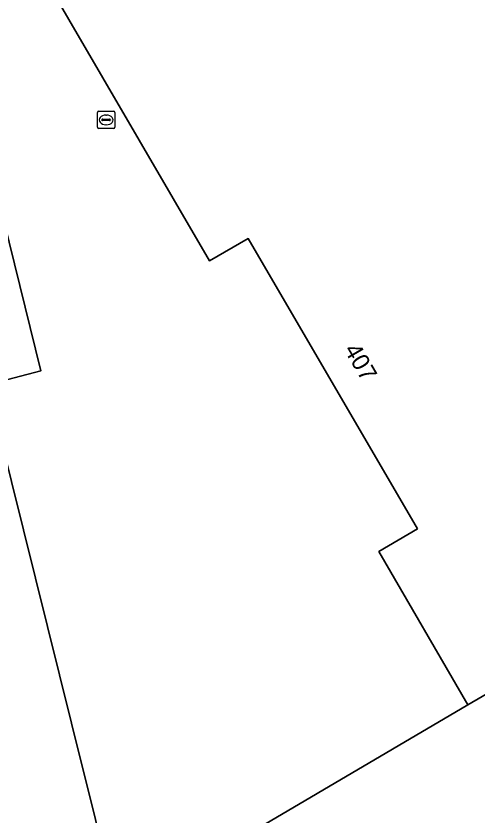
# Model space of a CAD drawing. Extents: x 161385 to 162589, y 388479 to 389756.
# Drawn here: x 162188.02 to 162214.6, y 388929.27 to 388975.29 of the extents above; entities that cross this region are included whole.
import ezdxf

# ---------------------------------------------------------------- set-up
doc = ezdxf.new("R2010")
doc.units = 0
for name, color, linetype in [('IMGEO_Erf', 7, 'Continuous'), ('IMGEO_Groenvoorziening', 7, 'Continuous'), ('IMGEO_Haag', 7, 'Continuous'), ('IMGEO_Pand', 7, 'Continuous'), ('IMGEO_Pand_nummerreeks', 7, 'Continuous'), ('IMGEO_Rijbaan_lokaal_gesloten', 7, 'Continuous'), ('IMGEO_Rioolput', 7, 'Continuous')]:
    doc.layers.add(name, color=color, linetype=linetype)

msp = doc.modelspace()

# ---------------------------------------------------------------- linework, layer by layer
at = {"layer": 'IMGEO_Erf'}
for points in [[(162205.565, 388889.805), (162226.358, 388916.854), (162240.417, 388950.904), (162224.076, 388941.428), (162229.276, 388932.462), (162223.571, 388918.583), (162206.409, 388908.625), (162196.702, 388925.403), (162214.07, 388935.626), (162208.932, 388944.442), (162211.169, 388945.746), (162201.412, 388962.483), (162199.18, 388961.18), (162188.976, 388978.704)], [(162183.768, 388977.824), (162184.88, 388973.335), (162189.456, 388954.856), (162186.365, 388954.055), (162191.224, 388934.569), (162202.309, 388890.111)]]:
    msp.add_lwpolyline(points, dxfattribs=at)
at = {"layer": 'IMGEO_Groenvoorziening'}
msp.add_lwpolyline([(162184.443, 388961.763), (162186.365, 388954.055), (162189.456, 388954.856), (162184.88, 388973.335)], dxfattribs=at)
at = {"layer": 'IMGEO_Haag'}
msp.add_lwpolyline([(162184.443, 388961.763), (162186.365, 388954.055), (162189.456, 388954.856), (162184.88, 388973.335)], dxfattribs=at)
at = {"layer": 'IMGEO_Pand'}
for points in [[(162260.806, 389000), (162264.508, 389009.017), (162258.602, 389019.221), (162225.572, 389000), (162188.976, 388978.704), (162199.18, 388961.18), (162201.412, 388962.483), (162211.169, 388945.746), (162208.932, 388944.442), (162214.07, 388935.626), (162224.076, 388941.428), (162240.417, 388950.904)], [(162224.076, 388941.428), (162214.07, 388935.626), (162196.702, 388925.403), (162206.409, 388908.625), (162223.571, 388918.583), (162229.276, 388932.462)]]:
    msp.add_lwpolyline(points, close=True, dxfattribs=at)
at = {"layer": 'IMGEO_Rijbaan_lokaal_gesloten'}
msp.add_lwpolyline([(162204.281, 388882.203), (162202.309, 388890.111), (162191.224, 388934.569), (162186.365, 388954.055), (162184.443, 388961.763)], dxfattribs=at)
at = {"layer": 'IMGEO_Rioolput'}
for p, q in [((162192.72, 388968.879), (162192.72, 388969.731)), ((162192.795, 388969.805), (162193.647, 388969.805)), ((162193.721, 388969.731), (162193.721, 388968.879)), ((162192.979, 388969.299), (162192.979, 388969.311)), ((162193.417, 388969.262), (162193.019, 388969.262)), ((162193.022, 388969.348), (162193.42, 388969.348)), ((162193.208, 388969.585), (162193.233, 388969.585)), ((162193.463, 388969.311), (162193.463, 388969.299)), ((162193.647, 388968.805), (162192.795, 388968.805)), ((162193.231, 388969.025), (162193.206, 388969.025))]:
    msp.add_line(p, q, dxfattribs=at)
for points in [[(162192.72, 388968.879), (162192.72, 388969.731)], [(162192.795, 388969.805), (162193.647, 388969.805)], [(162193.721, 388969.731), (162193.721, 388968.879)], [(162193.647, 388968.805), (162192.795, 388968.805)]]:
    msp.add_lwpolyline(points, dxfattribs=at)
for centre, radius, start, end in [((162192.797, 388969.729), 0.0765, 91.552, 178.448), ((162192.797, 388969.729), 0.0765, 91.552, 178.448), ((162193.645, 388969.729), 0.0765, 1.552, 88.448), ((162193.645, 388969.729), 0.0765, 1.552, 88.448), ((162193.019, 388969.308), 0.0403, 85.8775, 175.7526), ((162193.016, 388969.298), 0.0366, 178.938, 274.7102), ((162193.42, 388969.305), 0.043, 264.8664, 352.4533), ((162193.424, 388969.31), 0.0386, 1.7309, 96.639), ((162192.797, 388968.881), 0.0765, 181.552, 268.448), ((162192.797, 388968.881), 0.0765, 181.552, 268.448), ((162193.645, 388968.881), 0.0765, 271.552, 358.448), ((162193.645, 388968.881), 0.0765, 271.552, 358.448)]:
    msp.add_arc(centre, radius, start, end, dxfattribs=at)
for centre, major_axis, ratio, start_param, end_param in [((162193.207, 388969.305), (-0.387, 0.002), 0.722429, 4.712389, 7.853982), ((162193.232, 388969.305), (-0.39, 0.002), 0.717154, 1.570796, 4.712389)]:
    msp.add_ellipse(centre, major_axis=major_axis, ratio=ratio, start_param=start_param, end_param=end_param, dxfattribs=at)

# ---------------------------------------------------------------- texts
at = {"layer": 'IMGEO_Pand_nummerreeks'}
msp.add_text('407', height=1, rotation=300.2462, dxfattribs=at).set_placement((162206.907, 388956.071))

doc.saveas('drawing.dxf')
